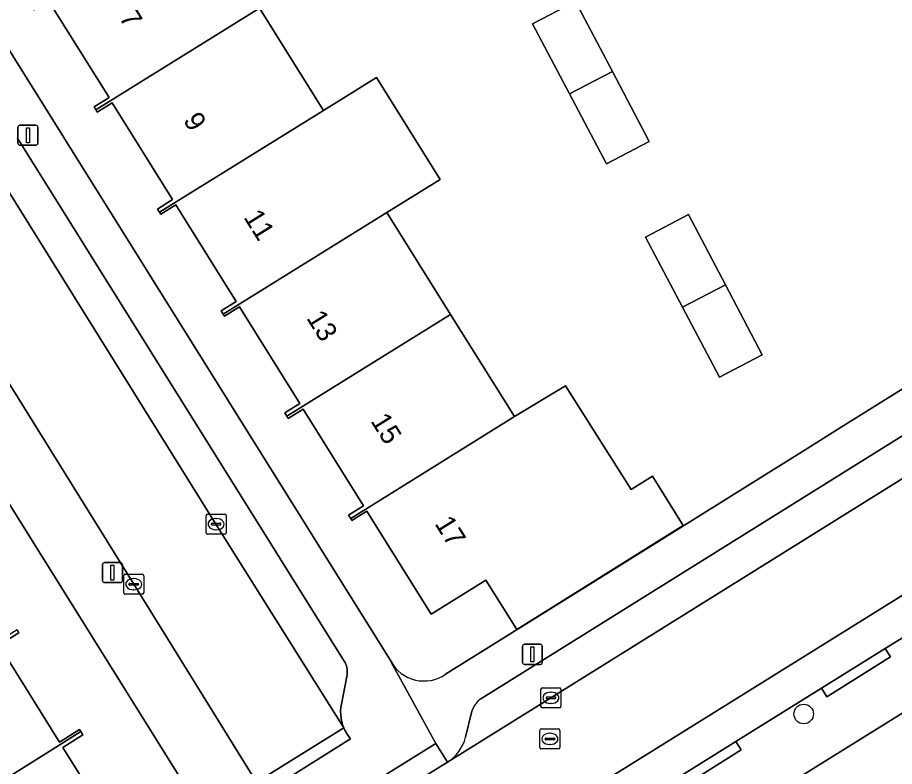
# Model space of a CAD drawing. Extents: x 158835 to 160077, y 386387 to 387778.
# Drawn here: x 159103.26 to 159146.99, y 387156.67 to 387194.01 of the extents above; entities that cross this region are included whole.
import ezdxf

# ---------------------------------------------------------------- set-up
doc = ezdxf.new("R2010")
doc.units = 0
for name, color, linetype in [('IMGEO_Boom', 7, 'Continuous'), ('IMGEO_Erf', 7, 'Continuous'), ('IMGEO_Kolk', 7, 'Continuous'), ('IMGEO_Lichtmast', 7, 'Continuous'), ('IMGEO_Muur', 7, 'Continuous'), ('IMGEO_Pand', 7, 'Continuous'), ('IMGEO_Pand_nummerreeks', 7, 'Continuous'), ('IMGEO_Parkeervlak_open', 7, 'Continuous'), ('IMGEO_Rijbaan_lokaal_open', 7, 'Continuous'), ('IMGEO_Rioolput', 7, 'Continuous'), ('IMGEO_Voetpad_open', 7, 'Continuous')]:
    doc.layers.add(name, color=color, linetype=linetype)

msp = doc.modelspace()

# ---------------------------------------------------------------- linework, layer by layer
at = {"layer": 'IMGEO_Boom'}
msp.add_circle((159142.461, 387159.284), 0.489, dxfattribs=at)
at = {"layer": 'IMGEO_Erf'}
for points in [[(159092.033, 387209.677), (159105.563, 387188.033), (159121.887, 387161.898)], [(159115.333, 387194.473), (159118.51, 387189.38), (159121.163, 387191.029), (159124.326, 387185.941), (159121.681, 387184.296), (159124.857, 387179.204), (159128.034, 387174.111), (159130.576, 387175.641), (159133.854, 387170.48), (159134.913, 387171.141), (159136.448, 387168.682), (159128.151, 387163.505), (159126.616, 387165.963), (159123.882, 387164.257), (159120.675, 387169.401), (159119.929, 387168.936), (159119.875, 387169.025), (159119.769, 387169.201), (159120.511, 387169.664), (159117.502, 387174.49), (159116.753, 387174.023), (159116.688, 387174.129), (159116.587, 387174.294), (159117.334, 387174.76), (159114.327, 387179.583), (159113.578, 387179.116), (159113.516, 387179.217), (159113.415, 387179.381), (159114.162, 387179.847), (159111.156, 387184.669), (159110.403, 387184.2), (159110.34, 387184.302), (159110.24, 387184.465), (159110.991, 387184.933), (159107.984, 387189.757), (159107.237, 387189.291), (159107.168, 387189.403), (159107.074, 387189.553), (159107.821, 387190.018), (159104.807, 387194.853)], [(159124.595, 387161.262), (159132.839, 387166.407), (159142.799, 387172.623), (159144.069, 387173.416), (159163.598, 387185.605), (159171.72, 387190.674)], [(159192.812, 387154.528), (159184.858, 387169.495), (159180.565, 387177.574), (159180.465, 387177.724), (159180.352, 387177.865), (159180.227, 387177.995), (159180.091, 387178.113), (159179.944, 387178.219), (159179.789, 387178.311), (159179.627, 387178.389), (159179.458, 387178.452), (159179.284, 387178.5), (159179.106, 387178.532), (159178.926, 387178.548), (159178.746, 387178.548), (159178.566, 387178.532), (159178.388, 387178.5), (159178.214, 387178.452), (159178.045, 387178.389), (159177.883, 387178.311), (159177.794, 387178.26), (159131.832, 387149.649)], [(159128.1, 387129.289), (159098.935, 387175.998)], [(159103.238, 387163.488), (159103.328, 387163.337), (159102.329, 387162.713), (159105.348, 387157.885), (159106.353, 387158.513), (159106.421, 387158.403), (159106.518, 387158.246), (159105.515, 387157.619), (159108.532, 387152.795)]]:
    msp.add_lwpolyline(points, dxfattribs=at)
for points in [[(159134.761, 387187.839), (159132.63, 387186.714), (159130.788, 387190.203), (159128.944, 387193.695), (159131.075, 387194.82), (159132.919, 387191.328)], [(159138.553, 387180.69), (159140.385, 387177.192), (159138.263, 387176.074), (159136.417, 387179.568), (159134.57, 387183.063), (159136.722, 387184.185)]]:
    msp.add_lwpolyline(points, close=True, dxfattribs=at)
msp.add_arc((159123.528, 387162.802), 1.873, 208.8484, 304.7177, dxfattribs=at)
at = {"layer": 'IMGEO_Kolk'}
for p, q in [((159112.66, 387168.324), (159112.66, 387169.176)), ((159112.735, 387169.25), (159113.587, 387169.25)), ((159113.148, 387169.03), (159113.173, 387169.03)), ((159113.661, 387169.176), (159113.661, 387168.324)), ((159112.919, 387168.744), (159112.919, 387168.756)), ((159113.357, 387168.707), (159112.959, 387168.707)), ((159112.962, 387168.793), (159113.36, 387168.793)), ((159113.403, 387168.756), (159113.403, 387168.744)), ((159113.587, 387168.25), (159112.735, 387168.25)), ((159113.171, 387168.47), (159113.146, 387168.47)), ((159108.553, 387165.329), (159108.553, 387166.181)), ((159108.628, 387166.255), (159109.48, 387166.255)), ((159109.041, 387166.035), (159109.066, 387166.035)), ((159109.554, 387166.181), (159109.554, 387165.329)), ((159108.812, 387165.749), (159108.812, 387165.761)), ((159109.25, 387165.712), (159108.852, 387165.712)), ((159108.855, 387165.798), (159109.253, 387165.798)), ((159109.064, 387165.475), (159109.039, 387165.475)), ((159109.296, 387165.761), (159109.296, 387165.749)), ((159109.48, 387165.255), (159108.628, 387165.255)), ((159129.355, 387159.664), (159129.355, 387160.516)), ((159129.43, 387160.59), (159130.282, 387160.59)), ((159129.843, 387160.37), (159129.868, 387160.37)), ((159130.356, 387160.516), (159130.356, 387159.664)), ((159129.614, 387160.084), (159129.614, 387160.096)), ((159130.052, 387160.047), (159129.654, 387160.047)), ((159129.657, 387160.133), (159130.055, 387160.133)), ((159129.866, 387159.81), (159129.841, 387159.81)), ((159130.098, 387160.096), (159130.098, 387160.084)), ((159130.282, 387159.59), (159129.43, 387159.59))]:
    msp.add_line(p, q, dxfattribs=at)
for points in [[(159112.66, 387168.324), (159112.66, 387169.176)], [(159112.735, 387169.25), (159113.587, 387169.25)], [(159113.661, 387169.176), (159113.661, 387168.324)], [(159113.587, 387168.25), (159112.735, 387168.25)], [(159108.553, 387165.329), (159108.553, 387166.181)], [(159108.628, 387166.255), (159109.48, 387166.255)], [(159109.554, 387166.181), (159109.554, 387165.329)], [(159109.48, 387165.255), (159108.628, 387165.255)], [(159129.355, 387159.664), (159129.355, 387160.516)], [(159129.43, 387160.59), (159130.282, 387160.59)], [(159130.356, 387160.516), (159130.356, 387159.664)], [(159130.282, 387159.59), (159129.43, 387159.59)]]:
    msp.add_lwpolyline(points, dxfattribs=at)
for centre, radius, start, end in [((159112.737, 387169.174), 0.0765, 91.552, 178.448), ((159112.737, 387169.174), 0.0765, 91.552, 178.448), ((159113.585, 387169.174), 0.0765, 1.552, 88.448), ((159113.585, 387169.174), 0.0765, 1.552, 88.448), ((159112.959, 387168.753), 0.0403, 85.8775, 175.7526), ((159112.956, 387168.743), 0.0366, 178.938, 274.7102), ((159113.36, 387168.75), 0.043, 264.8664, 352.4533), ((159113.364, 387168.755), 0.0386, 1.7309, 96.639), ((159112.737, 387168.326), 0.0765, 181.552, 268.448), ((159112.737, 387168.326), 0.0765, 181.552, 268.448), ((159113.585, 387168.326), 0.0765, 271.552, 358.448), ((159113.585, 387168.326), 0.0765, 271.552, 358.448), ((159108.63, 387166.179), 0.0765, 91.552, 178.448), ((159108.63, 387166.179), 0.0765, 91.552, 178.448), ((159109.478, 387166.179), 0.0765, 1.552, 88.448), ((159109.478, 387166.179), 0.0765, 1.552, 88.448), ((159108.852, 387165.758), 0.0403, 85.8775, 175.7526), ((159108.849, 387165.748), 0.0366, 178.938, 274.7102), ((159109.253, 387165.755), 0.043, 264.8664, 352.4533), ((159109.257, 387165.76), 0.0386, 1.7309, 96.639), ((159108.63, 387165.331), 0.0765, 181.552, 268.448), ((159108.63, 387165.331), 0.0765, 181.552, 268.448), ((159109.478, 387165.331), 0.0765, 271.552, 358.448), ((159109.478, 387165.331), 0.0765, 271.552, 358.448), ((159129.432, 387160.514), 0.0765, 91.552, 178.448), ((159129.432, 387160.514), 0.0765, 91.552, 178.448), ((159130.28, 387160.514), 0.0765, 1.552, 88.448), ((159130.28, 387160.514), 0.0765, 1.552, 88.448), ((159129.654, 387160.093), 0.0403, 85.8775, 175.7526), ((159129.651, 387160.083), 0.0366, 178.938, 274.7102), ((159130.055, 387160.09), 0.043, 264.8664, 352.4533), ((159130.059, 387160.095), 0.0386, 1.7309, 96.639), ((159129.432, 387159.666), 0.0765, 181.552, 268.448), ((159129.432, 387159.666), 0.0765, 181.552, 268.448), ((159130.28, 387159.666), 0.0765, 271.552, 358.448), ((159130.28, 387159.666), 0.0765, 271.552, 358.448)]:
    msp.add_arc(centre, radius, start, end, dxfattribs=at)
for centre, major_axis, ratio, start_param, end_param in [((159113.147, 387168.75), (-0.387, 0.002), 0.722429, 4.712389, 7.853982), ((159113.172, 387168.75), (-0.39, 0.002), 0.717154, 1.570796, 4.712389), ((159109.04, 387165.755), (-0.387, 0.002), 0.722429, 4.712389, 7.853982), ((159109.065, 387165.755), (-0.39, 0.002), 0.717154, 1.570796, 4.712389), ((159129.842, 387160.09), (-0.387, 0.002), 0.722429, 4.712389, 7.853982), ((159129.867, 387160.09), (-0.39, 0.002), 0.717154, 1.570796, 4.712389)]:
    msp.add_ellipse(centre, major_axis=major_axis, ratio=ratio, start_param=start_param, end_param=end_param, dxfattribs=at)
at = {"layer": 'IMGEO_Lichtmast'}
for p, q in [((159103.383, 387188.645), (159104.173, 387188.645)), ((159104.173, 387188.645), (159103.383, 387188.645)), ((159103.283, 387187.745), (159103.283, 387188.545)), ((159103.283, 387188.545), (159103.283, 387187.745)), ((159104.273, 387188.545), (159104.273, 387187.745)), ((159104.273, 387187.745), (159104.273, 387188.545)), ((159104.173, 387187.645), (159103.383, 387187.645)), ((159103.383, 387187.645), (159104.173, 387187.645)), ((159107.596, 387166.836), (159108.386, 387166.836)), ((159108.386, 387166.836), (159107.596, 387166.836)), ((159107.496, 387165.936), (159107.496, 387166.736)), ((159107.496, 387166.736), (159107.496, 387165.936)), ((159108.486, 387166.736), (159108.486, 387165.936)), ((159108.486, 387165.936), (159108.486, 387166.736)), ((159108.386, 387165.836), (159107.596, 387165.836)), ((159107.596, 387165.836), (159108.386, 387165.836)), ((159128.436, 387161.858), (159128.436, 387162.658)), ((159128.436, 387162.658), (159128.436, 387161.858)), ((159128.536, 387162.758), (159129.326, 387162.758)), ((159129.326, 387162.758), (159128.536, 387162.758)), ((159129.426, 387162.658), (159129.426, 387161.858)), ((159129.426, 387161.858), (159129.426, 387162.658)), ((159129.326, 387161.758), (159128.536, 387161.758)), ((159128.536, 387161.758), (159129.326, 387161.758))]:
    msp.add_line(p, q, dxfattribs=at)
for points in [[(159103.703, 387188.52), (159103.853, 387188.52), (159103.853, 387187.77), (159103.703, 387187.77), (159103.703, 387188.52)], [(159107.916, 387166.711), (159108.066, 387166.711), (159108.066, 387165.961), (159107.916, 387165.961), (159107.916, 387166.711)], [(159128.856, 387162.633), (159129.006, 387162.633), (159129.006, 387161.883), (159128.856, 387161.883), (159128.856, 387162.633)]]:
    msp.add_lwpolyline(points, dxfattribs=at)
for centre, start, end in [((159103.383, 387188.545), 90, 180), ((159103.383, 387188.545), 90, 180), ((159104.173, 387188.545), 0, 90), ((159104.173, 387188.545), 360, 90), ((159103.383, 387187.745), 180, 270), ((159103.383, 387187.745), 180, 270), ((159104.173, 387187.745), 270, 0), ((159104.173, 387187.745), 270, 0), ((159107.596, 387166.736), 90, 180), ((159107.596, 387166.736), 90, 180), ((159108.386, 387166.736), 0, 90), ((159108.386, 387166.736), 360, 90), ((159107.596, 387165.936), 180, 270), ((159107.596, 387165.936), 180, 270), ((159108.386, 387165.936), 270, 0), ((159108.386, 387165.936), 270, 0), ((159128.536, 387162.658), 90, 180), ((159128.536, 387162.658), 90, 180), ((159129.326, 387162.658), 0, 90), ((159129.326, 387162.658), 360, 90), ((159128.536, 387161.858), 180, 270), ((159128.536, 387161.858), 180, 270), ((159129.326, 387161.858), 270, 0), ((159129.326, 387161.858), 270, 0)]:
    msp.add_arc(centre, 0.1, start, end, dxfattribs=at)
at = {"layer": 'IMGEO_Muur'}
for points in [[(159144.069, 387173.416), (159163.598, 387185.605)], [(159132.839, 387166.407), (159142.799, 387172.623)]]:
    msp.add_lwpolyline(points, dxfattribs=at)
at = {"layer": 'IMGEO_Pand'}
for points in [[(159117.648, 387195.911), (159114.404, 387200.958), (159112.157, 387199.565), (159103.993, 387194.501), (159104.063, 387194.389), (159104.807, 387194.853), (159107.821, 387190.018), (159107.074, 387189.553), (159107.168, 387189.403), (159115.333, 387194.473)], [(159132.919, 387191.328), (159131.075, 387194.82), (159128.944, 387193.695), (159130.788, 387190.203)], [(159110.34, 387184.302), (159118.51, 387189.38), (159115.333, 387194.473), (159107.168, 387189.403), (159107.237, 387189.291), (159107.984, 387189.757), (159110.991, 387184.933), (159110.24, 387184.465)], [(159130.788, 387190.203), (159132.63, 387186.714), (159134.761, 387187.839), (159132.919, 387191.328)], [(159118.51, 387189.38), (159110.34, 387184.302), (159110.403, 387184.2), (159111.156, 387184.669), (159114.162, 387179.847), (159113.415, 387179.381), (159113.516, 387179.217), (159121.681, 387184.296), (159124.326, 387185.941), (159121.163, 387191.029)], [(159116.688, 387174.129), (159124.857, 387179.204), (159121.681, 387184.296), (159113.516, 387179.217), (159113.578, 387179.116), (159114.327, 387179.583), (159117.334, 387174.76), (159116.587, 387174.294)], [(159138.553, 387180.69), (159136.722, 387184.185), (159134.57, 387183.063), (159136.417, 387179.568)], [(159136.417, 387179.568), (159138.263, 387176.074), (159140.385, 387177.192), (159138.553, 387180.69)], [(159119.875, 387169.025), (159128.034, 387174.111), (159124.857, 387179.204), (159116.688, 387174.129), (159116.753, 387174.023), (159117.502, 387174.49), (159120.511, 387169.664), (159119.769, 387169.201)], [(159136.448, 387168.682), (159134.913, 387171.141), (159133.854, 387170.48), (159130.576, 387175.641), (159128.034, 387174.111), (159119.875, 387169.025), (159119.929, 387168.936), (159120.675, 387169.401), (159123.882, 387164.257), (159126.616, 387165.963), (159128.151, 387163.505)], [(159102.237, 387162.861), (159094.601, 387158.079), (159097.78, 387152.996), (159105.417, 387157.775), (159106.421, 387158.403), (159106.353, 387158.513), (159105.348, 387157.885), (159102.329, 387162.713), (159103.328, 387163.337), (159103.238, 387163.488)], [(159109.601, 387153.308), (159109.533, 387153.421), (159108.532, 387152.795), (159105.515, 387157.619), (159106.518, 387158.246), (159106.421, 387158.403), (159105.417, 387157.775), (159097.78, 387152.996), (159100.965, 387147.905), (159108.602, 387152.683)]]:
    msp.add_lwpolyline(points, close=True, dxfattribs=at)
at = {"layer": 'IMGEO_Parkeervlak_open'}
for points in [[(159102.608, 387185.676), (159113.156, 387168.75), (159119.526, 387158.595), (159119.479, 387158.718), (159119.429, 387158.89), (159119.394, 387159.067), (159119.375, 387159.245), (159119.372, 387159.425), (159119.385, 387159.605), (159119.414, 387159.782), (159119.676, 387161.162), (159119.692, 387161.249), (159119.701, 387161.336), (159119.702, 387161.425), (159119.695, 387161.513), (159119.68, 387161.599), (159119.657, 387161.685), (159119.627, 387161.768), (159119.589, 387161.847), (159119.545, 387161.924), (159103.339, 387187.862), (159103.297, 387187.933), (159103.249, 387188.001)], [(159124.698, 387156.88), (159129.852, 387160.089), (159149.771, 387172.508), (159168.759, 387184.361), (159173.218, 387187.157)], [(159169.681, 387187.071), (159126.365, 387160.043)], [(159176.063, 387183.08), (159170.211, 387179.417), (159151.418, 387167.712), (159128.969, 387153.744)], [(159132.379, 387153.68), (159135.892, 387155.914), (159139.082, 387157.916), (159143.344, 387160.566), (159146.528, 387162.551), (159151.219, 387165.464), (159154.416, 387167.461)], [(159125.917, 387159.427), (159125.598, 387158.123)]]:
    msp.add_lwpolyline(points, dxfattribs=at)
for centre, radius, start, end in [((159127.026, 387159.092), 1.158, 124.7755, 163.1698), ((159123.545, 387158.662), 2.123, 302.9056, 345.2812)]:
    msp.add_arc(centre, radius, start, end, dxfattribs=at)
at = {"layer": 'IMGEO_Rijbaan_lokaal_open'}
for points in [[(159186.985, 387195.824), (159182.901, 387193.183), (159182.797, 387193.116), (159182.679, 387193.04), (159174.039, 387187.668), (159173.315, 387187.218), (159173.218, 387187.157), (159168.759, 387184.361), (159149.771, 387172.508), (159129.852, 387160.089), (159124.698, 387156.88), (159121.887, 387155.13), (159117.406, 387152.34), (159119.888, 387148.372), (159130.485, 387131.344), (159141.225, 387114.195), (159142.231, 387112.577), (159142.423, 387112.239), (159142.602, 387111.89)], [(159128.969, 387153.744), (159151.418, 387167.712), (159170.211, 387179.417), (159176.063, 387183.08), (159176.9, 387183.614), (159185.441, 387188.891)]]:
    msp.add_lwpolyline(points, dxfattribs=at)
for points in [[(159102.608, 387185.676), (159100.153, 387189.591), (159095.851, 387186.92), (159101.246, 387178.309), (159109.051, 387165.756), (159115.179, 387155.878), (159119.526, 387158.595), (159113.156, 387168.75)], [(159119.526, 387158.595), (159115.179, 387155.878), (159115.522, 387155.326), (159119.859, 387158.041), (159119.689, 387158.285), (159119.584, 387158.484)]]:
    msp.add_lwpolyline(points, close=True, dxfattribs=at)
at = {"layer": 'IMGEO_Rioolput'}
for p, q in [((159129.305, 387157.616), (159129.305, 387158.468)), ((159129.38, 387158.542), (159130.232, 387158.542)), ((159130.306, 387158.468), (159130.306, 387157.616)), ((159129.564, 387158.036), (159129.564, 387158.048)), ((159129.607, 387158.085), (159130.005, 387158.085)), ((159129.793, 387158.322), (159129.818, 387158.322)), ((159130.048, 387158.048), (159130.048, 387158.036)), ((159130.002, 387157.999), (159129.604, 387157.999)), ((159129.816, 387157.762), (159129.791, 387157.762)), ((159130.232, 387157.542), (159129.38, 387157.542))]:
    msp.add_line(p, q, dxfattribs=at)
for points in [[(159129.305, 387157.616), (159129.305, 387158.468)], [(159129.38, 387158.542), (159130.232, 387158.542)], [(159130.306, 387158.468), (159130.306, 387157.616)], [(159130.232, 387157.542), (159129.38, 387157.542)]]:
    msp.add_lwpolyline(points, dxfattribs=at)
for centre, radius, start, end in [((159129.382, 387158.466), 0.0765, 91.552, 178.448), ((159129.382, 387158.466), 0.0765, 91.552, 178.448), ((159130.23, 387158.466), 0.0765, 1.552, 88.448), ((159130.23, 387158.466), 0.0765, 1.552, 88.448), ((159129.604, 387158.045), 0.0403, 85.8775, 175.7526), ((159129.601, 387158.035), 0.0366, 178.938, 274.7102), ((159130.005, 387158.042), 0.043, 264.8664, 352.4533), ((159130.009, 387158.047), 0.0386, 1.7309, 96.639), ((159129.382, 387157.618), 0.0765, 181.552, 268.448), ((159129.382, 387157.618), 0.0765, 181.552, 268.448), ((159130.23, 387157.618), 0.0765, 271.552, 358.448), ((159130.23, 387157.618), 0.0765, 271.552, 358.448)]:
    msp.add_arc(centre, radius, start, end, dxfattribs=at)
for centre, major_axis, ratio, start_param, end_param in [((159129.792, 387158.042), (-0.387, 0.002), 0.722429, 4.712389, 7.853982), ((159129.817, 387158.042), (-0.39, 0.002), 0.717154, 1.570796, 4.712389)]:
    msp.add_ellipse(centre, major_axis=major_axis, ratio=ratio, start_param=start_param, end_param=end_param, dxfattribs=at)
at = {"layer": 'IMGEO_Voetpad_open'}
for points in [[(159105.563, 387188.033), (159092.033, 387209.677), (159091.098, 387211.176), (159089.329, 387214.01), (159086.64, 387218.318)], [(159179.845, 387194.213), (159179.937, 387193.926), (159180.023, 387193.767), (159180.099, 387193.628), (159175.753, 387190.945), (159175.449, 387191.521), (159174.824, 387192.704), (159171.72, 387190.674), (159163.598, 387185.605), (159144.069, 387173.416), (159142.799, 387172.623), (159132.839, 387166.407), (159124.595, 387161.262)], [(159103.249, 387188.001), (159103.297, 387187.933), (159103.339, 387187.862), (159119.545, 387161.924), (159119.589, 387161.847), (159119.627, 387161.768), (159119.657, 387161.685), (159119.68, 387161.599), (159119.695, 387161.513), (159119.702, 387161.425), (159119.701, 387161.336), (159119.692, 387161.249), (159119.676, 387161.162), (159119.414, 387159.782), (159119.385, 387159.605), (159119.372, 387159.425), (159119.375, 387159.245), (159119.394, 387159.067), (159119.429, 387158.89), (159119.479, 387158.718), (159119.526, 387158.595), (159119.584, 387158.484), (159119.689, 387158.285), (159119.859, 387158.041), (159115.522, 387155.326)], [(159121.257, 387156.034), (159124.117, 387157.814), (159121.891, 387161.871), (159121.887, 387161.898), (159105.563, 387188.033)], [(159126.365, 387160.043), (159169.681, 387187.071)], [(159096.051, 387180.526), (159098.894, 387176.097), (159098.935, 387175.998), (159128.1, 387129.289), (159128.897, 387128.013), (159128.914, 387127.985), (159134.38, 387119.23), (159135.688, 387117.136), (159138.894, 387112.002), (159140.608, 387109.256)], [(159174.403, 387179.897), (159169.734, 387176.991), (159169.998, 387176.567), (159166.805, 387174.574), (159166.541, 387174.998), (159161.863, 387172.098), (159162.127, 387171.674), (159158.931, 387169.68), (159158.667, 387170.104), (159154.416, 387167.461), (159154.68, 387167.037), (159151.483, 387165.04), (159151.219, 387165.464), (159146.528, 387162.551), (159146.792, 387162.127), (159143.608, 387160.142), (159143.344, 387160.566), (159139.082, 387157.916), (159139.347, 387157.493), (159136.157, 387155.491), (159135.892, 387155.914), (159132.379, 387153.68)], [(159119.888, 387148.372), (159117.406, 387152.34), (159116.825, 387153.274), (159115.522, 387155.326), (159115.179, 387155.878), (159109.051, 387165.756), (159101.246, 387178.309)], [(159131.832, 387149.649), (159177.794, 387178.26)], [(159121.887, 387161.898), (159121.891, 387161.871), (159124.117, 387157.814), (159124.698, 387156.88)], [(159125.598, 387158.123), (159125.917, 387159.427)]]:
    msp.add_lwpolyline(points, dxfattribs=at)
for points in [[(159143.344, 387160.566), (159143.608, 387160.142), (159146.792, 387162.127), (159146.528, 387162.551)], [(159121.887, 387155.13), (159124.698, 387156.88), (159124.117, 387157.814), (159121.257, 387156.034), (159116.825, 387153.274), (159117.406, 387152.34)], [(159139.082, 387157.916), (159135.892, 387155.914), (159136.157, 387155.491), (159139.347, 387157.493)]]:
    msp.add_lwpolyline(points, close=True, dxfattribs=at)
for centre, radius, start, end in [((159123.528, 387162.802), 1.873, 208.8484, 304.7177), ((159127.026, 387159.092), 1.158, 124.7755, 163.1698), ((159123.545, 387158.662), 2.123, 302.9056, 345.2812)]:
    msp.add_arc(centre, radius, start, end, dxfattribs=at)

# ---------------------------------------------------------------- texts
at = {"layer": 'IMGEO_Pand_nummerreeks'}
for s, rotation, p in [('7', 301.9422, (159108.298, 387194.015)), ('9', 301.9424, (159111.494, 387188.89)), ('11', 301.9422, (159114.507, 387184.059)), ('13', 301.9424, (159117.641, 387179.028)), ('15', 301.9424, (159120.837, 387173.902)), ('17', 301.9422, (159124.033, 387168.777))]:
    msp.add_text(s, height=1, rotation=rotation, dxfattribs=at).set_placement(p)

doc.saveas('drawing.dxf')
